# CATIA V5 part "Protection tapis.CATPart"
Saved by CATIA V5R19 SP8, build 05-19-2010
Part number: Protection tapis
Nomenclature: 47
Material "Plastique": density 1200 kg/m3, Young's modulus 2.2e+09 Pa, Poisson ratio 0.38, thermal expansion 6.84e-05 1/K
Bounding box of the stored display mesh (mm): x 0 to 1100, y 0 to 80, z -50 to 0
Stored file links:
  C:\Users\rphgr\Desktop\0_Tapis_TC520B_vitesse\Protection tapis.CATPart
  D:\Programmes\DassaultSysteme\win_b64\startup\materials\French\Catalog.CATMaterial
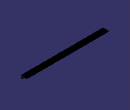
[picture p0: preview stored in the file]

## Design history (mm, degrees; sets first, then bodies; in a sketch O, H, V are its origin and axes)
AxisSystem1: origin (0, 0, 0), X (1, 0, 0), Y (0, 1, 0), Z (0, 0, 1)
Body1 (main body), material "Plastique"
  Sketch1 on YZ plane of AxisSystem1, origin (0, 0, 0), H (0, 1, 0), V (0, 0, 1)
    point P1 (0, -50)
    line L1 (0, -50) -> (0, -6)
    arc A1 centre (6, -6) radius 6 from (0, -6) to (6, 0) cw
    point P4 (6, 0)
    line L2 (6, 0) -> (80, 0)
    point P5 (43, -12)
    point P6 (80, 0)
    line L3 (80, 0) -> (80, -4)
    distance L2 P1 = 50
    distance P6 L1 = 80
    radius A1 = 6
    distance L1 P5 = 43
    length L3 = 4
    coincidence: P1 V, P4 H
    vertical: L1 V, L3 V
    tangency: A1 L1, L2 A1
    horizontal: L2 H
  Pad1: profile Sketch1, direction (1, 0, 0), length 1100, thin wall 2
  Sketch2 on end face of Pad1, origin (1100, 0, 0), H (0, 1, 0), V (0, 0, 1)
    line L1 (2, -12) -> (27, -12)
    point P1 (2, -12)
    point P2 (27, -12)
    reference projected line E1 (6, 0) -> (80, 0) from edge [end face of Pad1 | face of Pad1]
    line L2 (44, -12) -> (67, -12)
    point P3 (44, -12)
    arc A1 centre (78, -13.05) radius 11.05 from (78, -2) to (67, -12) ccw
    point P5 (78, -13.05)
    point P6 (78, -2)
    reference intersected line E2 (78, -4) -> (78, -2) from face of Pad1
    reference intersected line E3 (78, -2) -> (6, -2) from face of Pad1
    reference intersected line E4 (78, -4) -> (78, -2) from face of Pad1
    reference intersected line E5 (2, -6) -> (2, -50) from face of Pad1
    distance L1 E1 = 12
    length L2 = 23
    length L1 = 25
    distance P2 P3 = 17
    horizontal: L1 H, L2 H
    coincidence: P3 L1, P6 E2, P5 E4, E5 P1
    tangency: A1 E3
  Pad2: profile Sketch2, direction (-1, 0, 0), up to start face of Pad1, thin wall 2
  Sketch3 on face of Pad1, origin (1100, 0, 0), H (0, 1, 0), V (0, 0, 1)
    line L1 (13, -10) -> (13, -2)
    point P1 (13, -10)
    point P2 (13, -2)
    line L2 (23, -10) -> (23, -2)
    point P3 (23, -10)
    point P4 (23, -2)
    line L3 (47.5, -10) -> (47.5, -2)
    point P5 (47.5, -10)
    point P6 (47.5, -2)
    line L4 (61.5, -10) -> (61.5, -2)
    point P7 (61.5, -10)
    point P8 (61.5, -2)
    reference intersected line E1 (78, -2) -> (6, -2) from face of Pad1
    reference intersected line E2 (78, -2) -> (6, -2) from face of Pad1
    reference intersected line E3 (78, -2) -> (6, -2) from face of Pad1
    reference intersected line E4 (78, -2) -> (6, -2) from face of Pad1
    reference intersected line E5 (44, -10) -> (65.3114, -10) from face of Pad2
    reference intersected line E6 (44, -10) -> (65.3114, -10) from face of Pad2
    reference intersected line E7 (2, -10) -> (27, -10) from face of Pad2
    reference projected line E8 (2, -10) -> (27, -10) from edge [face of Pad1 | face of Pad2]
    reference intersected line E9 (2, -6) -> (2, -50) from face of Pad1
    reference intersected line E10 (44, -12) -> (44, -10) from face of Pad2
    distance L1 E9 = 11
    distance L1 L2 = 10
    distance L3 E10 = 3.5
    distance L4 L3 = 14
    vertical: L1 V, L2 V, L3 V
    coincidence: P2 E1, P4 E2, P6 E3, P8 E4, P5 E5, P7 E6, P3 E7, P1 E8
  Pad3: profile Sketch3, direction (1, 0, 0), up to face of Pad1, thin wall 2
  Sketch4 on face of Pad1, origin (1100, 0, 0), H (0, 1, 0), V (0, 0, 1)
    line L1 (7.7113, 0) -> (8, -0.5)
    point P2 (8, -0.5)
    line L2 (8, -0.5) -> (8.2887, 0)
    line L3 (8.2887, 0) -> (7.7113, 0)
    reference intersected line E1 (6, 0) -> (80, 0) from face of Pad1
    reference intersected line E2 (0, -50) -> (0, -6) from face of Pad1
    angle L1 L2 = 60
    angle L1 L3 = 60
    distance L3 P2 = 0.5
    distance P2 E2 = 8
    horizontal: L3 H
    coincidence: L3 E1
  Pocket1: profile Sketch4, direction (-1, 0, 0), through (limit type 3)
  RectPattern1: of Pocket1, direction 1 instances 36, spacing 2, along edge [face of Pad1 | face of Pad1]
